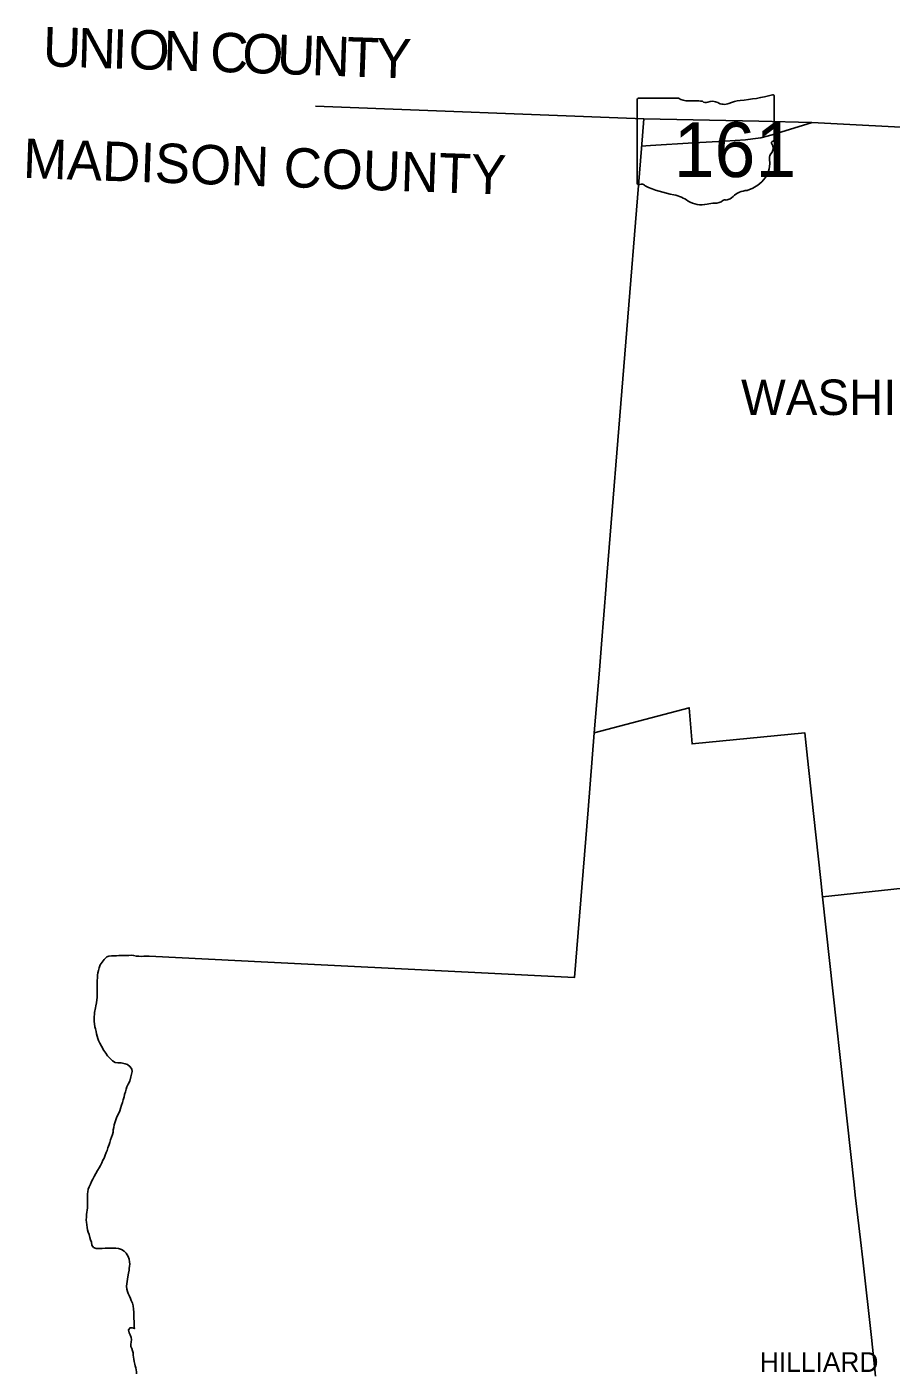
# Model space of a CAD drawing. Extents: x -1146 to -445, y -1283 to -822.
# Drawn here: x -1067.1 to -1012.2, y -1003.9 to -918.5 of the extents above; entities that cross this region are included whole.
import ezdxf

# ---------------------------------------------------------------- set-up
doc = ezdxf.new("R2010")
doc.units = 0
for name, color, linetype in [('GM_X_Adjacent_County', 7, 'Continuous'), ('GM_X_Adjacent_County_Text', 7, 'Continuous'), ('GM_X_Corporation_Text', 7, 'Continuous'), ('GM_X_County', 7, 'Continuous'), ('GM_X_State_Route', 7, 'Continuous'), ('GM_X_State_Shield', 7, 'Continuous'), ('GM_X_Township', 7, 'Continuous'), ('GM_X_Township_Text', 7, 'Continuous')]:
    doc.layers.add(name, color=color, linetype=linetype)

msp = doc.modelspace()

# ---------------------------------------------------------------- linework, layer by layer
at = {"layer": 'GM_X_Adjacent_County'}
msp.add_line((-1027.92, -924.353), (-1048.759, -923.551), dxfattribs=at)
at = {"layer": 'GM_X_County'}
msp.add_lwpolyline([(-1060.1, -1003.98), (-1060.103, -1003.85), (-1060.117, -1003.724), (-1060.146, -1003.598), (-1060.184, -1003.472), (-1060.218, -1003.347), (-1060.257, -1003.191), (-1060.28, -1003.04), (-1060.299, -1002.909), (-1060.307, -1002.779), (-1060.326, -1002.648), (-1060.354, -1002.522), (-1060.408, -1002.366), (-1060.457, -1002.23), (-1060.475, -1002.094), (-1060.449, -1001.964), (-1060.427, -1001.799), (-1060.435, -1001.673), (-1060.499, -1001.502), (-1060.567, -1001.376), (-1060.615, -1001.184), (-1060.508, -1001.045), (-1060.383, -1001.061), (-1060.238, -1001.098), (-1060.246, -1000.962), (-1060.255, -1000.807), (-1060.263, -1000.646), (-1060.281, -1000.465), (-1060.278, -1000.204), (-1060.281, -1000.064), (-1060.289, -999.858), (-1060.312, -999.667), (-1060.365, -999.486), (-1060.439, -999.314), (-1060.492, -999.188), (-1060.551, -999.047), (-1060.634, -998.871), (-1060.673, -998.74), (-1060.712, -998.594), (-1060.73, -998.418), (-1060.723, -998.258), (-1060.696, -998.112), (-1060.671, -997.968), (-1060.649, -997.827), (-1060.606, -997.593), (-1060.573, -997.396), (-1060.565, -997.28), (-1060.544, -997.145), (-1060.538, -997.004), (-1060.551, -996.864), (-1060.575, -996.698), (-1060.628, -996.522), (-1060.761, -996.31), (-1060.89, -996.198), (-1061.065, -996.086), (-1061.25, -996.029), (-1061.42, -996.002), (-1061.616, -995.995), (-1061.742, -996.004), (-1061.912, -996.002), (-1062.098, -995.995), (-1062.293, -996.024), (-1062.485, -996.029), (-1062.654, -996.01), (-1062.825, -995.956), (-1062.935, -995.8), (-1062.968, -995.624), (-1063.021, -995.463), (-1063.06, -995.317), (-1063.118, -995.141), (-1063.176, -994.98), (-1063.21, -994.829), (-1063.233, -994.688), (-1063.261, -994.522), (-1063.285, -994.351), (-1063.288, -994.216), (-1063.286, -994.02), (-1063.269, -993.87), (-1063.252, -993.724), (-1063.236, -993.584), (-1063.219, -993.429), (-1063.216, -993.138), (-1063.219, -992.962), (-1063.222, -992.831), (-1063.221, -992.706), (-1063.214, -992.56), (-1063.197, -992.415), (-1063.166, -992.265), (-1063.104, -992.11), (-1063.026, -991.94), (-1062.954, -991.76), (-1062.877, -991.626), (-1062.785, -991.446), (-1062.677, -991.256), (-1062.585, -991.077), (-1062.472, -990.897), (-1062.385, -990.747), (-1062.303, -990.578), (-1062.231, -990.418), (-1062.159, -990.288), (-1062.087, -990.103), (-1062.029, -989.928), (-1061.973, -989.798), (-1061.916, -989.643), (-1061.838, -989.418), (-1061.801, -989.288), (-1061.759, -989.123), (-1061.697, -988.958), (-1061.62, -988.793), (-1061.593, -988.633), (-1061.576, -988.483), (-1061.549, -988.342), (-1061.517, -988.172), (-1061.45, -987.987), (-1061.418, -987.852), (-1061.346, -987.672), (-1061.253, -987.482), (-1061.171, -987.282), (-1061.124, -987.132), (-1061.056, -986.927), (-1060.994, -986.752), (-1060.942, -986.587), (-1060.89, -986.397), (-1060.858, -986.257), (-1060.811, -986.082), (-1060.769, -985.911), (-1060.722, -985.766), (-1060.64, -985.602), (-1060.537, -985.412), (-1060.468, -985.137), (-1060.379, -984.791), (-1060.403, -984.64), (-1060.501, -984.484), (-1060.671, -984.352), (-1060.821, -984.3), (-1060.991, -984.258), (-1061.088, -984.234), (-1061.292, -984.23), (-1061.462, -984.208), (-1061.627, -984.106), (-1061.796, -983.953), (-1061.94, -983.796), (-1062.058, -983.629), (-1062.187, -983.452), (-1062.319, -983.18), (-1062.423, -982.998), (-1062.511, -982.821), (-1062.565, -982.695), (-1062.603, -982.544), (-1062.632, -982.409), (-1062.67, -982.258), (-1062.709, -982.087), (-1062.747, -981.951), (-1062.775, -981.76), (-1062.784, -981.619), (-1062.787, -981.493), (-1062.79, -981.328), (-1062.778, -981.162), (-1062.767, -981.037), (-1062.703, -980.757), (-1062.677, -980.616), (-1062.644, -980.426), (-1062.627, -980.245), (-1062.61, -980.09), (-1062.604, -979.954), (-1062.6, -979.603), (-1062.603, -979.407), (-1062.606, -979.277), (-1062.604, -979.116), (-1062.598, -978.986), (-1062.586, -978.86), (-1062.574, -978.68), (-1062.552, -978.524), (-1062.516, -978.379), (-1062.478, -978.204), (-1062.406, -978.029), (-1062.273, -977.845), (-1062.156, -977.675), (-1061.994, -977.516), (-1061.867, -977.468), (-1061.697, -977.454), (-1061.521, -977.451), (-1061.405, -977.448), (-1061.373, -977.446), (-1061.219, -977.439), (-1061.044, -977.436), (-1060.908, -977.432), (-1060.727, -977.429), (-1060.587, -977.431), (-1060.431, -977.417), (-1060.295, -977.429), (-1060.115, -977.476), (-1059.954, -977.478), (-1059.779, -977.49), (-1059.638, -977.481), (-1059.442, -977.473), (-1059.307, -977.474), (-1051.768, -977.849), (-1038.643, -978.502), (-1032.321, -978.816), (-1031.462, -968.198), (-1031.067, -963.308), (-1030.744, -959.324), (-1030.61, -957.669), (-1030.31, -953.948), (-1030.305, -953.894), (-1028.071, -926.227), (-1027.92, -924.353), (-1020.628, -924.507), (-1017.275, -924.587), (-1009.61, -924.974)], dxfattribs=at)
at = {"layer": 'GM_X_State_Route'}
msp.add_lwpolyline([(-1028.1, -926.08), (-1027.497, -926.051), (-1024.768, -925.871), (-1022.782, -925.757), (-1021.483, -925.675), (-1021.018, -925.618), (-1020.511, -925.545), (-1019.784, -925.365), (-1018.624, -925.005), (-1017.32, -924.601), (-1017.275, -924.587)], dxfattribs=at)
at = {"layer": 'GM_X_State_Shield'}
for p, q in [((-1028.357, -923.132), (-1028.357, -928.415)), ((-1025.723, -923.041), (-1028.271, -923.041)), ((-1019.656, -925.673), (-1019.656, -922.91)), ((-1019.657, -925.673), (-1019.656, -925.673))]:
    msp.add_line(p, q, dxfattribs=at)
for centre, major_axis, start_param, end_param in [((-1028.257, -923.12), (0.101, 0), 1.712693, 3.28349), ((-1025.116, -922.427), (0.978, 0), 4.042523, 4.731795), ((-1024.792, -926.007), (3.51, 0), 1.404758, 1.657858), ((-1023.581, -923.704), (0.586, 0), 0.950623, 2.079405), ((-1021.578, -924.654), (1.856, 0), 1.699011, 2.107814), ((-1022.755, -915.838), (9.227, 0), 4.814394, 5.042369), ((-1019.752, -922.898), (0.0969, 0), 6.141152, 7.989035), ((-1023.995, -923.093), (0.282, 0), 3.836095, 5.185415), ((-1022.824, -922.866), (0.705, 0), 4.081561, 5.145723), ((-1019.678, -925.876), (0.15, 0), 1.883978, 3.671073), ((-1019.759, -925.684), (0.104, 0), 5.05454, 6.418171), ((-1019.309, -926.83), (0.655, 0), 2.387724, 3.262537), ((-1020.632, -926.226), (0.9, 0), 5.934695, 6.695948), ((-1022.238, -927.182), (2.308, 0), 5.101752, 6.440018), ((-1028.256, -928.426), (0.102, 0), 3.00124, 4.508301), ((-1028.241, -927.886), (0.776, 0), 4.665946, 4.897461), ((-1028.082, -928.72), (0.28, 0), 0.519207, 1.627899), ((-1024.549, -923.973), (6.663, 0), 4.195997, 4.488961), ((-1026.536, -930.788), (2.085, 0), 0.823519, 1.323587), ((-1021.265, -929.898), (1.264, 0), 1.647645, 2.488434), ((-1024.281, -928.746), (1.323, 0), 4.026481, 4.996735), ((-1023.516, -930.572), (1.087, 0), 1.495662, 1.94098), ((-1023.42, -929.141), (0.705, 0), 4.691044, 5.507374), ((-1022.782, -929.653), (0.198, 0), 1.147584, 2.315152), ((-1022.867, -928.927), (0.746, 0), 4.937069, 5.64225)]:
    msp.add_ellipse(centre, major_axis=major_axis, ratio=0.8, start_param=start_param, end_param=end_param, dxfattribs=at)
at = {"layer": 'GM_X_Township'}
for points in [[(-1031.067, -963.308), (-1025.049, -961.716), (-1024.864, -964.002), (-1017.71, -963.305), (-1017.539, -964.902), (-1017.161, -968.422), (-1016.7, -972.672), (-1016.586, -973.717)], [(-1013.224, -1004.12), (-1013.486, -1001.672), (-1014.04, -996.744), (-1014.19, -995.472), (-1014.515, -992.632), (-1014.593, -991.97), (-1016.586, -973.717), (-1010.894, -973.097)]]:
    msp.add_lwpolyline(points, dxfattribs=at)

# ---------------------------------------------------------------- texts
at = {"layer": 'GM_X_Adjacent_County_Text'}
for s, rotation, p in [('U', 358.17045, (-1066.068, -921.008)), ('N', 358.17016, (-1063.862, -921.078)), ('I', 358.1643, (-1061.657, -921.149)), ('O', 358.13244, (-1060.64, -921.181)), ('N', 358.08015, (-1058.435, -921.253)), ('C', 358.02251, (-1055.467, -921.353)), ('O', 358.01795, (-1053.43, -921.424)), ('U', 358.01794, (-1051.225, -921.5)), ('N', 358.01793, (-1049.02, -921.576)), ('T', 358.01813, (-1046.814, -921.653)), ('Y', 358.01813, (-1044.949, -921.717)), ('MADISON COUNTY', 358.00662, (-1067.329, -928.094))]:
    msp.add_text(s, height=2.5, rotation=rotation, dxfattribs=at).set_placement(p)
at = {"layer": 'GM_X_Corporation_Text'}
msp.add_text('HILLIARD', height=1.25, rotation=0.00001, dxfattribs=at).set_placement((-1020.569, -1003.849))
at = {"layer": 'GM_X_State_Shield'}
msp.add_text('161', height=3.4805, dxfattribs=at).set_placement((-1026.031, -928.042))
at = {"layer": 'GM_X_Township_Text'}
msp.add_text('WASHINGTON', height=2.25, rotation=0.00001, dxfattribs=at).set_placement((-1021.761, -943.14))

doc.saveas('drawing.dxf')
